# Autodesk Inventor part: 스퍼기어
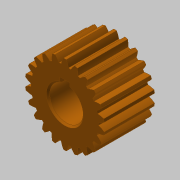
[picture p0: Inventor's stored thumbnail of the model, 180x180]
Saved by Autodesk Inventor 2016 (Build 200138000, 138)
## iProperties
Created: 2019-03
Part Number: 스퍼기어
Material: 강철
Document SubType Name: Modeling
Designer: mduedu
Categories: <?xml version="1.0" encoding="UTF-16"?> <MemberInstance><Categories><FamilyTemplate><FamilyTemplateParameter ValueType="xs:double" Id="1" ObjectReferenceKey="da
Density: 1 g/cm^3
Appearance: 주황색
CustomPartVersion: 1
Author: mduedu
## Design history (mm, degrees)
sketch "Sketch1"
  geometry: C1 r 23.6 at (0, 0)
  constraints: 1 centre point
  dimensions: "d0" = 47.2 diameter of C1 (= da_da)
extrude "Extrusion1" new body sketch "Sketch1" distance "d1" = 30 (= da_b); taper "d2" = 0 deg
workplane "Work Plane2"
sketch "Sketch2"
  geometry: C1 r 23.6 at (0, 0) reference; C2 r 22 at (0, 0)
  constraints: 1 centre point, 1 coincident
  dimensions: "d3" = 44 diameter of C2 (= da_dw)
feature "피치 지름" sketch "Sketch2" dims "d4" = 10, "d5" = 0
workplane "Work Plane8"
workplane "Work Plane9"
feature "스퍼 기어" dims "d49" = 20, "da_b" = 30, "da_d" = 44, "da_aw" = 44, "da_da" = 47.2, "da_df" = 40.172, "da_dw" = 44, angle "da_beta" = 0 deg, "da_lefttooth" = 0, "da_righttooth" = 0
sketch "스케치3"
  geometry: L1 (-3, 9.539)-(3, 9.539); L2 (3, 9.539)-(3, 12.8); L3 (3, 12.8)-(-3, 12.8); L4 (-3, 12.8)-(-3, 9.539); A1 r 10 centre (0, 0) between (-3, 9.539) and (3, 9.539); 1 further point
  constraints: 8 end point, 2 parallel, 2 point on circle, 1 centre point, 1 coincident, 1 horizontal, 1 perpendicular
  dimensions: "d49" = 20 diameter of A1; "d50" = 6 distance of L2.end L3.end; "d51" = 22.8 dimension on A1 L3
extrude "돌출2" cut sketch "스케치3" stored distance "d52" = 10; taper "d53" = 0 deg
chamfer "모따기1" distance "d54" = 1; stored, may be unused: second distance "d55" = 2, angle "d56" = 45 deg
body "Solid1"
body "Srf1"
other parameters: "d16" = 44 (= da_aw), "d17" = 0, "d34" = 1.428 (computed from da_z), "d39" = 0, "d41" = 0, "d43" = 44 (= da_aw), "d46" = 44 (= da_aw), "d47" = 0, "d48" = 0
